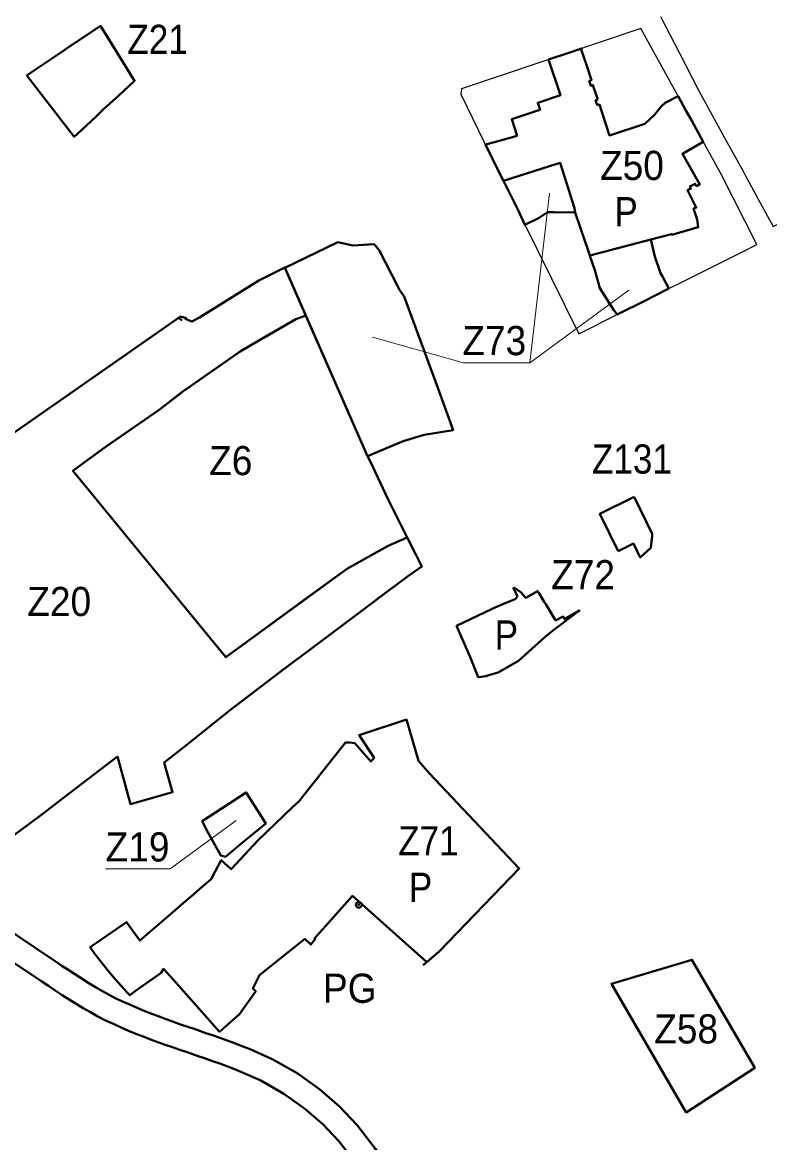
# Model space of a CAD drawing. Extents: x -650276 to -642489, y -1074311 to -1066658.
# Drawn here: x -648043 to -647428, y -1071620 to -1070699 of the extents above; entities that cross this region are included whole.
import ezdxf

# ---------------------------------------------------------------- set-up
doc = ezdxf.new("R2010")
doc.units = 0
doc.header["$LTSCALE"] = 9.6
doc.header["$PDMODE"] = 32
doc.header["$PDSIZE"] = 4.8
for name, color, linetype, lineweight in [('2', 7, 'Continuous', 40), ('42', 7, 'Continuous', 25), ('44', 7, 'Continuous', 40), ('45', 7, 'Continuous', 40), ('46', 7, 'Continuous', 13), ('60', 7, 'Continuous', 35)]:
    doc.layers.add(name, color=color, linetype=linetype, lineweight=lineweight)

msp = doc.modelspace()

# ---------------------------------------------------------------- linework, layer by layer
at = {"layer": '2'}
for points in [[(-647539.818, -1071089.2), (-647568.01, -1071102.98), (-647553.01, -1071133.68)], [(-647525.1, -1071121.25), (-647524.95, -1071119.68), (-647539.817, -1071089.199)], [(-647553.01, -1071133.68), (-647540.48, -1071127.55), (-647534.851, -1071139.015), (-647526.04, -1071130.94), (-647525.1, -1071121.25)]]:
    msp.add_lwpolyline(points, dxfattribs=at)
at = {"layer": '42'}
for points in [[(-647518.19, -1070693.93), (-647502.59, -1070724.13), (-647486.84, -1070754.54), (-647464.3, -1070795.6), (-647450.23, -1070821.25), (-647448.84, -1070823.79), (-647437.79, -1070844.12), (-647425.58, -1070866.7), (-647401.15, -1070854.25), (-647365.48, -1070835.85), (-647334.27, -1070819.86), (-647332.51, -1070817.97), (-647332.25, -1070813.72), (-647345.18, -1070779.89), (-647346.96, -1070775.41), (-647365.94, -1070725.08), (-647367.67, -1070720.73), (-647377.04, -1070696.22)], [(-647717.363, -1071306.29), (-647727.368, -1071272.362), (-647766.35, -1071285.11), (-647753.89, -1071303.94), (-647756.67, -1071306.77), (-647769.85, -1071291.91), (-647774.14, -1071291.34), (-647777.4, -1071291.32), (-647815.95, -1071339.71), (-647820.93, -1071344.25), (-647849.86, -1071372.18), (-647867.45, -1071390.95), (-647871.68, -1071395.59), (-647879.76, -1071387.96), (-647885.05, -1071397.88), (-647888.11, -1071403.61), (-647895.29, -1071409.81), (-647904.3, -1071417.58), (-647911.04, -1071423.39), (-647913.31, -1071425.35), (-647921.96, -1071432.81), (-647946.78, -1071454.23), (-647957.906, -1071439.06), (-647974.66, -1071450.62), (-647977.28, -1071452.43), (-647979.88, -1071454.22), (-647982.46, -1071456), (-647985.06, -1071457.79), (-647987.8, -1071459.68), (-647984, -1071465), (-647977.13, -1071474.05), (-647972.76, -1071479)], [(-647710.546, -1071472.023), (-647700.078, -1071462.96), (-647634.524, -1071394.901), (-647708.429, -1071316.821), (-647717.363, -1071306.29)], [(-647803.1, -1071452.66), (-647771.82, -1071417.42), (-647710.546, -1071472.023)], [(-647848.4, -1071482.78), (-647810.97, -1071452.92), (-647806.15, -1071457.48)], [(-647806.15, -1071457.48), (-647802.53, -1071453.19), (-647803.1, -1071452.66)], [(-647972.76, -1071479), (-647967.13, -1071486.01), (-647957.07, -1071497.13), (-647955.14, -1071499.23), (-647950.56, -1071495.85), (-647944.81, -1071491.78), (-647939.31, -1071487.88), (-647933.88, -1071484.04), (-647931.17, -1071482.12), (-647929.26, -1071480.77), (-647927.2, -1071477.54), (-647919.22, -1071486.5), (-647881.16, -1071529.25)], [(-647881.16, -1071529.25), (-647876.27, -1071524.96), (-647864.69, -1071514.65), (-647851.45, -1071495.96), (-647853.77, -1071493.78), (-647848.4, -1071482.78)]]:
    msp.add_lwpolyline(points, dxfattribs=at)
msp.add_lwpolyline([(-647534.33, -1070703.84), (-647567.08, -1070714.8), (-647583.22, -1070720.2), (-647651.82, -1070743.17), (-647682.08, -1070753.29), (-647682.67, -1070757.67), (-647663.71, -1070796.77), (-647585.55, -1070954.94), (-647553.94, -1070939.11), (-647532.58, -1070928.392), (-647511.37, -1070917.79), (-647501.26, -1070912.72), (-647450.8, -1070887.42), (-647438.82, -1070881.43), (-647467.89, -1070824.15), (-647480.13, -1070802.09), (-647503.76, -1070759.31)], close=True, dxfattribs=at)
at = {"layer": '44'}
for points in [[(-647834.953, -1071553.406), (-647837.929, -1071551.872), (-647843.891, -1071549), (-647849.898, -1071546.282), (-647855.937, -1071543.707), (-647861.998, -1071541.254), (-647868.073, -1071538.911), (-647874.155, -1071536.658), (-647880.233, -1071534.48), (-647886.305, -1071532.36), (-647892.363, -1071530.282), (-647901.28, -1071527.249), (-647907.294, -1071525.204), (-647913.282, -1071523.152), (-647919.238, -1071521.081), (-647925.157, -1071518.976), (-647931.035, -1071516.824), (-647936.866, -1071514.613), (-647942.644, -1071512.329), (-647948.363, -1071509.96), (-647954.016, -1071507.496), (-647959.792, -1071504.833), (-647966.547, -1071501.883), (-647972.035, -1071499.009), (-647977.67, -1071495.885), (-647983.266, -1071492.628), (-647988.829, -1071489.259), (-647994.366, -1071485.79), (-647999.887, -1071482.241), (-648005.399, -1071478.627), (-648010.917, -1071474.963), (-648016.446, -1071471.268), (-648063.593, -1071439.723)], [(-648074.86, -1071456.248), (-648027.562, -1071487.894), (-648022.005, -1071491.607), (-648016.415, -1071495.321), (-648010.777, -1071499.017), (-648005.082, -1071502.678), (-647999.319, -1071506.287), (-647993.478, -1071509.826), (-647987.55, -1071513.275), (-647981.525, -1071516.615), (-647975.201, -1071519.929), (-647967.982, -1071523.081), (-647962.2, -1071525.746), (-647956.187, -1071528.368), (-647950.146, -1071530.869), (-647944.088, -1071533.263), (-647938.019, -1071535.566), (-647931.945, -1071537.788), (-647925.874, -1071539.949), (-647919.808, -1071542.058), (-647913.756, -1071544.132), (-647907.72, -1071546.185), (-647898.827, -1071549.208), (-647892.847, -1071551.26), (-647886.903, -1071553.336), (-647881.001, -1071555.45), (-647875.147, -1071557.619), (-647869.348, -1071559.856), (-647863.611, -1071562.177), (-647857.944, -1071564.594), (-647847.103, -1071569.497)], [(-647725.629, -1071678.373), (-647735.352, -1071657.117), (-647741.34, -1071644.028), (-647753.065, -1071625.201), (-647767.784, -1071606.225), (-647782.408, -1071590.847), (-647798.911, -1071576.526), (-647817.375, -1071563.458), (-647834.953, -1071553.406)], [(-647847.103, -1071569.497), (-647828.141, -1071580.34), (-647811.272, -1071592.28), (-647796.24, -1071605.324), (-647782.97, -1071619.278)], [(-647782.97, -1071619.278), (-647769.498, -1071636.647), (-647758.994, -1071653.513), (-647743.48, -1071687.426), (-647611.514, -1071974.086)]]:
    msp.add_lwpolyline(points, dxfattribs=at)
at = {"layer": '45'}
for p, q in [((-647914.73, -1070941.682), (-647912.347, -1070944.065)), ((-647914.73, -1070941.682), (-647912.347, -1070944.065)), ((-647713.442, -1071474.53), (-647700.078, -1071462.96)), ((-647713.442, -1071474.53), (-647700.078, -1071462.96))]:
    msp.add_line(p, q, dxfattribs=at)
for points in [[(-648032.601, -1070737.472), (-648039.82, -1070742.33), (-648000.85, -1070792.88), (-647994.63, -1070787.05), (-647982.89, -1070776.05), (-647976.97, -1070770.51), (-647964.21, -1070758.77), (-647951.11, -1070746.78), (-647979.17, -1070701.65), (-648008.28, -1070720.96), (-648009.29, -1070721.79), (-648019.49, -1070728.65)], [(-647827.363, -1070900.725), (-647783.95, -1070879.58), (-647771.47, -1070882.27), (-647753.81, -1070881.3), (-647749.75, -1070886.1), (-647734.48, -1070915.94), (-647732.97, -1070918.87), (-647729.27, -1070924.35), (-647701.45, -1070999.4), (-647688.9, -1071034.18), (-647712.74, -1071037.99), (-647730.17, -1071043.21), (-647759.52, -1071055.67)], [(-647827.363, -1070900.725), (-647783.95, -1070879.58), (-647771.47, -1070882.27), (-647753.81, -1070881.3), (-647749.75, -1070886.1), (-647734.48, -1070915.94), (-647732.97, -1070918.87), (-647729.27, -1070924.35), (-647701.45, -1070999.4), (-647688.9, -1071034.18), (-647712.74, -1071037.99), (-647730.17, -1071043.21), (-647759.52, -1071055.67)], [(-648001.766, -1071068.02), (-648001.922, -1071067.83), (-647973.304, -1071046.814), (-647930.96, -1071017.383), (-647912.11, -1071003.11), (-647906.9, -1070999.39), (-647875.248, -1070977.173), (-647864.03, -1070969.3), (-647843.928, -1070957.692), (-647818.33, -1070942.91), (-647810.243, -1070939.825), (-647759.52, -1071055.67), (-647757.19, -1071059.66), (-647742.64, -1071090.72), (-647726.74, -1071122.48), (-647742.35, -1071129.43), (-647775.982, -1071148.001), (-647775.982, -1071148.001), (-647875.939, -1071221.104)], [(-647974.66, -1071450.62), (-647977.28, -1071452.43), (-647979.88, -1071454.22), (-647982.46, -1071456), (-647985.06, -1071457.79), (-647987.8, -1071459.68), (-647984, -1071465), (-647977.13, -1071474.05), (-647972.76, -1071479), (-647967.13, -1071486.01), (-647957.07, -1071497.13), (-647955.14, -1071499.23), (-647950.56, -1071495.85), (-647944.81, -1071491.78), (-647939.31, -1071487.88), (-647933.88, -1071484.04), (-647931.17, -1071482.12), (-647929.26, -1071480.77), (-647927.2, -1071477.54), (-647919.22, -1071486.5), (-647881.16, -1071529.25), (-647876.27, -1071524.96), (-647864.69, -1071514.65), (-647851.45, -1071495.96), (-647853.77, -1071493.78), (-647848.4, -1071482.78), (-647810.97, -1071452.92), (-647806.15, -1071457.48), (-647802.53, -1071453.19), (-647803.1, -1071452.66), (-647771.82, -1071417.42), (-647710.546, -1071472.023), (-647700.078, -1071462.96), (-647634.524, -1071394.901), (-647708.429, -1071316.821), (-647717.363, -1071306.29), (-647727.368, -1071272.362), (-647766.35, -1071285.11), (-647753.89, -1071303.94), (-647756.67, -1071306.77), (-647769.85, -1071291.91), (-647774.14, -1071291.34), (-647777.4, -1071291.32), (-647815.95, -1071339.71), (-647820.93, -1071344.25), (-647849.86, -1071372.18), (-647867.45, -1071390.95), (-647871.68, -1071395.59), (-647879.76, -1071387.96), (-647885.05, -1071397.88), (-647888.11, -1071403.61), (-647895.29, -1071409.81), (-647904.3, -1071417.58), (-647911.04, -1071423.39), (-647913.31, -1071425.35), (-647921.96, -1071432.81), (-647946.78, -1071454.23), (-647957.906, -1071439.06)], [(-647974.66, -1071450.62), (-647977.28, -1071452.43), (-647979.88, -1071454.22), (-647982.46, -1071456), (-647985.06, -1071457.79), (-647987.8, -1071459.68), (-647984, -1071465), (-647977.13, -1071474.05), (-647972.76, -1071479), (-647967.13, -1071486.01), (-647957.07, -1071497.13), (-647955.14, -1071499.23), (-647950.56, -1071495.85), (-647944.81, -1071491.78), (-647939.31, -1071487.88), (-647933.88, -1071484.04), (-647931.17, -1071482.12), (-647929.26, -1071480.77), (-647927.2, -1071477.54), (-647919.22, -1071486.5), (-647881.16, -1071529.25), (-647876.27, -1071524.96), (-647864.69, -1071514.65), (-647851.45, -1071495.96), (-647853.77, -1071493.78), (-647848.4, -1071482.78), (-647810.97, -1071452.92), (-647806.15, -1071457.48), (-647802.53, -1071453.19), (-647803.1, -1071452.66), (-647771.82, -1071417.42), (-647710.546, -1071472.023), (-647700.078, -1071462.96), (-647634.524, -1071394.901), (-647708.429, -1071316.821), (-647717.363, -1071306.29), (-647727.368, -1071272.362), (-647766.35, -1071285.11), (-647753.89, -1071303.94), (-647756.67, -1071306.77), (-647769.85, -1071291.91), (-647774.14, -1071291.34), (-647777.4, -1071291.32), (-647815.95, -1071339.71), (-647820.93, -1071344.25), (-647849.86, -1071372.18), (-647867.45, -1071390.95), (-647871.68, -1071395.59), (-647879.76, -1071387.96), (-647885.05, -1071397.88), (-647888.11, -1071403.61), (-647895.29, -1071409.81), (-647904.3, -1071417.58), (-647911.04, -1071423.39), (-647913.31, -1071425.35), (-647921.96, -1071432.81), (-647946.78, -1071454.23), (-647957.906, -1071439.06)], [(-647879.09, -1071345.3), (-647895.37, -1071355.96), (-647890.7, -1071365.52), (-647880.14, -1071384.32), (-647876.34, -1071385.2), (-647862.25, -1071373.55), (-647859.44, -1071371.23), (-647843.23, -1071357.82), (-647859.31, -1071332.34)], [(-647879.09, -1071345.3), (-647895.37, -1071355.96), (-647890.7, -1071365.52), (-647880.14, -1071384.32), (-647876.34, -1071385.2), (-647862.25, -1071373.55), (-647859.44, -1071371.23), (-647843.23, -1071357.82), (-647859.31, -1071332.34)], [(-647497.04, -1071595.66), (-647440.67, -1071558.93), (-647492.3, -1071470), (-647495.85, -1071471.06), (-647558.654, -1071489.738)], [(-647497.04, -1071595.66), (-647440.67, -1071558.93), (-647492.3, -1071470), (-647495.85, -1071471.06), (-647558.654, -1071489.738)]]:
    msp.add_lwpolyline(points, close=True, dxfattribs=at)
for points in [[(-647569.92, -1070762.24), (-647573.88, -1070750.25), (-647575.58, -1070750.83), (-647576.81, -1070746.86), (-647575.09, -1070746.33), (-647578.79, -1070734.33), (-647583.38, -1070720.9), (-647583.22, -1070720.2), (-647593.6, -1070723.68), (-647610.33, -1070729.28), (-647600.53, -1070758.65), (-647619.2, -1070764.85), (-647617.36, -1070770.69)], [(-647636.12, -1070792.13), (-647654.89, -1070797.23), (-647662.26, -1070799.23), (-647650.908, -1070822.34), (-647647.405, -1070829.08), (-647609.58, -1070817.06), (-647600.8, -1070814.27), (-647588.89, -1070851.67), (-647588.4, -1070855.25), (-647584.6, -1070866.3), (-647580.22, -1070879.3), (-647578.703, -1070883.851), (-647578.703, -1070883.851), (-647576.469, -1070890.564), (-647526.13, -1070877.41), (-647509.1, -1070872.96), (-647508.96, -1070873.41), (-647487.16, -1070867.32), (-647487.91, -1070860.91), (-647490.92, -1070851.82), (-647488.8, -1070851.12), (-647494.1, -1070840.58), (-647495.93, -1070836.86), (-647493.16, -1070835.5), (-647494.03, -1070833.64), (-647489.55, -1070831.53), (-647488.75, -1070833.37), (-647485.9, -1070832), (-647500.07, -1070806.87), (-647500.07, -1070806.87), (-647483.16, -1070797.07), (-647492.81, -1070779.18), (-647492.81, -1070779.18), (-647497.227, -1070771.165), (-647503.76, -1070759.31), (-647514.49, -1070764.93), (-647517.61, -1070767.89), (-647523.07, -1070774.86), (-647531.05, -1070782.23), (-647560.06, -1070791.72), (-647566.26, -1070773.148)], [(-647570.27, -1070766.86), (-647571.63, -1070762.82), (-647569.92, -1070762.24)], [(-647566.26, -1070773.148), (-647568.55, -1070766.29), (-647570.27, -1070766.86)], [(-647617.36, -1070770.69), (-647619.12, -1070771.28), (-647640.66, -1070778.47), (-647636.12, -1070792.13)], [(-647588.4, -1070855.25), (-647588.89, -1070851.67), (-647600.8, -1070814.27), (-647609.58, -1070817.06), (-647647.405, -1070829.08)], [(-647588.4, -1070855.25), (-647588.89, -1070851.67), (-647600.8, -1070814.27), (-647609.58, -1070817.06), (-647647.405, -1070829.08)], [(-647647.405, -1070829.08), (-647635.11, -1070853.786), (-647629.92, -1070865.35), (-647618.01, -1070859.42), (-647611.3, -1070854.9), (-647605.64, -1070854.99), (-647588.4, -1070855.25)], [(-647647.405, -1070829.08), (-647635.11, -1070853.786), (-647629.92, -1070865.35), (-647618.01, -1070859.42), (-647611.3, -1070854.9), (-647605.64, -1070854.99), (-647588.4, -1070855.25)], [(-647511.37, -1070917.79), (-647516.66, -1070907.8), (-647518.12, -1070905.05), (-647522.74, -1070891.48), (-647526.13, -1070877.41), (-647576.469, -1070890.564)], [(-647576.469, -1070890.564), (-647576.43, -1070890.68), (-647572.32, -1070902.72), (-647568.2, -1070917.54), (-647556.52, -1070935.59), (-647553.94, -1070939.11)], [(-648060.01, -1071374.69), (-648038.18, -1071358.51), (-648025.39, -1071348.76), (-648009.31, -1071336.48), (-647994.31, -1071325.03), (-647965.26, -1071302.86), (-647954.38, -1071342), (-647919.88, -1071332.23), (-647925.6, -1071311.69), (-647926.69, -1071307.81), (-647910.73, -1071295.08), (-647907.92, -1071292.84), (-647888.77, -1071277.56), (-647873.25, -1071265.17), (-647831.565, -1071233.455), (-647801.178, -1071210.742), (-647756.03, -1071176.76), (-647750.34, -1071172.5), (-647726.56, -1071154.68), (-647714.71, -1071146.51), (-647714.71, -1071146.51), (-647719.73, -1071136.48), (-647726.74, -1071122.48), (-647742.35, -1071129.43), (-647775.982, -1071148.001), (-647808.402, -1071171.711), (-647848.51, -1071201.045), (-647875.939, -1071221.104), (-648001.766, -1071068.02), (-648001.922, -1071067.83), (-647977.41, -1071049.74), (-647930.96, -1071017.383), (-647911.838, -1071002.919), (-647912.11, -1071003.11), (-647864.29, -1070969.503), (-647838.842, -1070954.778), (-647818.33, -1070942.91), (-647810.243, -1070939.825), (-647827.527, -1070900.351), (-647848.89, -1070911.21), (-647897.76, -1070941.62), (-647904.13, -1070944.78), (-647909.42, -1070942.63), (-647908.63, -1070942.1), (-647913.45, -1070940.79), (-648062.53, -1071044.59)], [(-647553.94, -1070939.11), (-647553.94, -1070939.11), (-647550.59, -1070937.45), (-647533.31, -1070928.79), (-647511.37, -1070917.79)], [(-647629.09, -1071172.4), (-647632.93, -1071167.71), (-647638.46, -1071163.89), (-647639.32, -1071164.22), (-647635.93, -1071171.22)], [(-647629.09, -1071172.4), (-647632.93, -1071167.71), (-647638.46, -1071163.89), (-647639.32, -1071164.22), (-647635.93, -1071171.22)], [(-647635.93, -1071171.22), (-647637.87, -1071173.29), (-647646.09, -1071176.68), (-647653.85, -1071179.87), (-647662.634, -1071183.968)], [(-647635.93, -1071171.22), (-647637.87, -1071173.29), (-647646.09, -1071176.68), (-647653.85, -1071179.87), (-647662.634, -1071183.968)], [(-647612.695, -1071177.542), (-647613.91, -1071175.57), (-647614.732, -1071174.222), (-647618.446, -1071168.166), (-647618.469, -1071168.129), (-647618.77, -1071167.64), (-647619.264, -1071166.832), (-647619.34, -1071166.709), (-647628.39, -1071172.05), (-647629.09, -1071172.4)], [(-647612.695, -1071177.542), (-647613.91, -1071175.57), (-647614.732, -1071174.222), (-647618.446, -1071168.166), (-647618.469, -1071168.129), (-647618.77, -1071167.64), (-647619.264, -1071166.832), (-647619.34, -1071166.709), (-647628.39, -1071172.05), (-647629.09, -1071172.4)], [(-647674.6, -1071221.71), (-647668.226, -1071237.571), (-647667.77, -1071237.5), (-647661.99, -1071236.62), (-647658.78, -1071235.63), (-647651.93, -1071233.57), (-647635.17, -1071224.18), (-647613.09, -1071204.33), (-647607.02, -1071199.34), (-647584.92, -1071182.54), (-647597.164, -1071189.857), (-647598.215, -1071187.608), (-647604.576, -1071190.781)], [(-647674.6, -1071221.71), (-647668.226, -1071237.571), (-647667.77, -1071237.5), (-647661.99, -1071236.62), (-647658.78, -1071235.63), (-647651.93, -1071233.57), (-647635.17, -1071224.18), (-647613.09, -1071204.33), (-647607.02, -1071199.34), (-647584.92, -1071182.54), (-647597.164, -1071189.857), (-647598.215, -1071187.608), (-647604.576, -1071190.781)], [(-647604.576, -1071190.781), (-647604.888, -1071190.272), (-647612.695, -1071177.542)], [(-647604.576, -1071190.781), (-647604.888, -1071190.272), (-647612.695, -1071177.542)], [(-647662.634, -1071183.968), (-647686.01, -1071195.35), (-647686.01, -1071195.35)], [(-647662.634, -1071183.968), (-647686.01, -1071195.35), (-647686.01, -1071195.35)], [(-647686.01, -1071195.35), (-647686.01, -1071195.35), (-647674.6, -1071221.71)], [(-647686.01, -1071195.35), (-647686.01, -1071195.35), (-647674.6, -1071221.71)]]:
    msp.add_lwpolyline(points, dxfattribs=at)
msp.add_point((-647766.557, -1071424.793), dxfattribs=at)
at = {"layer": '46'}
for points in [[(-647544.337, -1070919.163), (-647625.809, -1070978.773), (-647609.46, -1070839.305), (-647625.809, -1070978.773), (-647680.348, -1070978.773), (-647755.299, -1070957.715)], [(-647544.337, -1070919.163), (-647625.809, -1070978.773), (-647609.46, -1070839.305), (-647625.809, -1070978.773), (-647680.348, -1070978.773), (-647755.299, -1070957.715)], [(-647974.97, -1071395.111), (-647921.786, -1071395.111), (-647867.57, -1071355.322)], [(-647974.97, -1071395.111), (-647921.786, -1071395.111), (-647867.57, -1071355.322)]]:
    msp.add_lwpolyline(points, dxfattribs=at)

# ---------------------------------------------------------------- texts
at = {"layer": '2', "width": 0.9}
msp.add_text('Z131', height=24, dxfattribs=at).set_placement((-647574.644, -1071069.985))
at = {"layer": '46'}
for s, width, p in [('Z21', 0.9, (-647957.11, -1070724.677)), ('Z50', 0.95, (-647567.967, -1070828.405)), ('Z50', 0.95, (-647567.967, -1070828.405)), ('Z73', 0.95, (-647681.324, -1070972.53)), ('Z73', 0.95, (-647681.324, -1070972.53)), ('Z6', 0.95, (-647889.738, -1071071.271)), ('Z72', 0.95, (-647608.212, -1071165.192)), ('Z72', 0.95, (-647608.212, -1071165.192)), ('Z20', 0.95, (-648039.444, -1071187.201)), ('Z19', 0.95, (-647974.958, -1071389.14)), ('Z19', 0.95, (-647974.958, -1071389.14)), ('Z71', 0.9, (-647734.152, -1071384.125)), ('Z71', 0.9, (-647734.152, -1071384.125)), ('Z58', 0.95, (-647523.363, -1071538.888)), ('Z58', 0.95, (-647523.363, -1071538.888))]:
    msp.add_text(s, height=24, dxfattribs=dict(at, width=width)).set_placement(p)
at = {"layer": '60'}
for s, width, p in [('P', 0.9, (-647556.162, -1070866.47)), ('P', 0.9, (-647556.162, -1070866.47)), ('P', 0.9, (-647654.706, -1071214.743)), ('P', 0.9, (-647654.706, -1071214.743)), ('P', 0.9, (-647725.36, -1071422.368)), ('P', 0.9, (-647725.36, -1071422.368)), ('PG', 0.95, (-647796.031, -1071505.454)), ('PG', 0.95, (-647796.031, -1071505.454))]:
    msp.add_text(s, height=24, dxfattribs=dict(at, width=width)).set_placement(p)

doc.saveas('drawing.dxf')
